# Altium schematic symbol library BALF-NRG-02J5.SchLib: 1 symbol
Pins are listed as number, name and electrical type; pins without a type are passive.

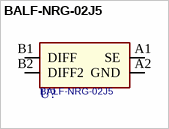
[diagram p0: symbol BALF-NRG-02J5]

## BALF-NRG-02J5
designator U?
footprint ST_CSP4N100x40P2x2_138x85x34
pins: A1 SE, A2 GND, B1 DIFF, B2 DIFF2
